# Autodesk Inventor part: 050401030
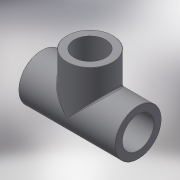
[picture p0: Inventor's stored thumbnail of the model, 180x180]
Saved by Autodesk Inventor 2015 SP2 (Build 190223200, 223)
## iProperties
Created: 2017-10
Part Number: 050401030
Material: Generic
Description: PLASSON THREADED TEE PVC 3"
Document SubType Name: Modeling
Designer: KIM
Density: 1 g/cm^3
Appearance: Default
Author: KIM
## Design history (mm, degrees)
derived "050401.ipt"
feature "Solid1::050401.ipt"
feature "Solid2::050401.ipt"
tag "TaggingFeature1"
body "Solid1"
other parameters: "d0" = 199, "d1" = 108, "d2" = 33, "d4" = 84.926, "d5" = 76.4334, "d7" = 0.84926, "d8" = 33, "d9" = 99.5, "d10" = 108, "d15" = 0, "d18" = 84.926, "d24" = 0.84926, "d30" = 84.926, "d31" = 33, "d32" = 0, "d33" = 76.4334, "d35" = 0, "d36" = 4.2463, "G_" = 84.926, "E_" = 108, "H_" = 199, "lt_" = 33
